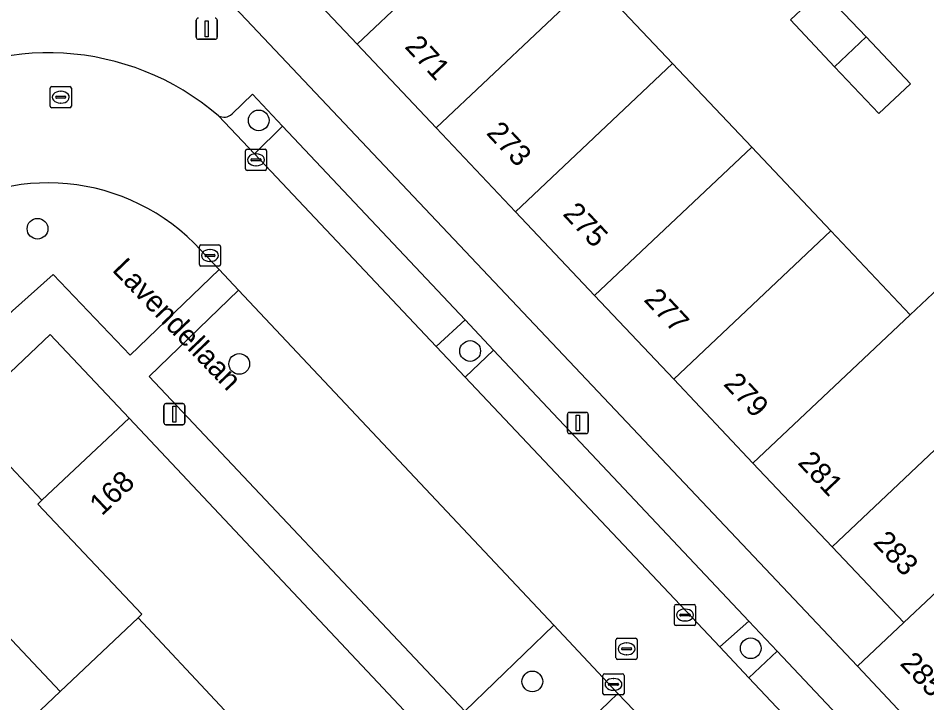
# Model space of a CAD drawing. Extents: x 162542 to 163147, y 380779 to 381521.
# Drawn here: x 162864.72 to 162907.61, y 381395.12 to 381427.46 of the extents above; entities that cross this region are included whole.
import ezdxf

# ---------------------------------------------------------------- set-up
doc = ezdxf.new("R2010")
doc.units = 0
for name, color, linetype in [('IMGEO_Boom', 7, 'Continuous'), ('IMGEO_Erf', 7, 'Continuous'), ('IMGEO_Groenvoorziening', 7, 'Continuous'), ('IMGEO_Kolk', 7, 'Continuous'), ('IMGEO_Lichtmast', 7, 'Continuous'), ('IMGEO_Openbare_ruimte_label', 7, 'Continuous'), ('IMGEO_Pand', 7, 'Continuous'), ('IMGEO_Pand_nummerreeks', 7, 'Continuous'), ('IMGEO_Parkeervlak_open', 7, 'Continuous'), ('IMGEO_Rijbaan_lokaal_open', 7, 'Continuous'), ('IMGEO_Rioolput', 7, 'Continuous'), ('IMGEO_Voetpad_open', 7, 'Continuous')]:
    doc.layers.add(name, color=color, linetype=linetype)

msp = doc.modelspace()

# ---------------------------------------------------------------- linework, layer by layer
at = {"layer": 'IMGEO_Boom'}
for centre in [(162876.075, 381422.632), (162865.636, 381417.515), (162886.055, 381411.739), (162875.156, 381411.126), (162899.298, 381397.696), (162888.991, 381396.129)]:
    msp.add_circle(centre, 0.489, dxfattribs=at)
at = {"layer": 'IMGEO_Erf'}
for points in [[(162861.159, 381432.002), (162869.05, 381439.12), (162869.767, 381438.361), (162876.917, 381445.114), (162880.655, 381441.156), (162884.393, 381437.198), (162888.132, 381433.24), (162891.87, 381429.282), (162895.608, 381425.324), (162899.346, 381421.365), (162903.084, 381417.407), (162906.823, 381413.449), (162908.963, 381415.47)], [(162851.755, 381366.101), (162878.09, 381390.885), (162870.382, 381399.141), (162866.702, 381395.654), (162862.661, 381391.825)]]:
    msp.add_lwpolyline(points, dxfattribs=at)
for points in [[(162888.193, 381418.32), (162884.455, 381422.279), (162880.718, 381426.238), (162876.98, 381430.196), (162873.243, 381434.155), (162869.505, 381438.114), (162867.324, 381436.054), (162904.333, 381396.849), (162906.52, 381398.909), (162903.143, 381402.486), (162899.406, 381406.444), (162895.668, 381410.403), (162891.93, 381414.362)], [(162902.654, 381428.781), (162904.744, 381426.573), (162906.833, 381424.364), (162905.354, 381422.952), (162903.258, 381425.167), (162901.17, 381427.375)], [(162862.119, 381408.635), (162865.839, 381404.688), (162869.957, 381408.567), (162866.239, 381412.517)]]:
    msp.add_lwpolyline(points, close=True, dxfattribs=at)
at = {"layer": 'IMGEO_Groenvoorziening'}
for points in [[(162877.202, 381422.355), (162875.775, 381423.871), (162874.815, 381422.945)], [(162874.173, 381422.854), (162875.878, 381421.045), (162877.202, 381422.355)], [(162859.95, 381417.481), (162863.931, 381413.146), (162864.454, 381413.638), (162866.374, 381415.356), (162870.009, 381411.547), (162874.208, 381415.582)], [(162874.208, 381415.582), (162873.032, 381416.833)]]:
    msp.add_lwpolyline(points, dxfattribs=at)
for points in [[(162875.124, 381414.608), (162870.912, 381410.533), (162885.812, 381394.721), (162890.007, 381398.784)], [(162887.154, 381411.783), (162885.816, 381413.205), (162884.448, 381411.957), (162885.817, 381410.504)], [(162892.608, 381395.151), (162893.031, 381395.568), (162890.007, 381398.784), (162885.812, 381394.721), (162888.818, 381391.531)], [(162900.543, 381397.562), (162899.205, 381398.982), (162897.835, 381397.758), (162899.21, 381396.299)]]:
    msp.add_lwpolyline(points, close=True, dxfattribs=at)
for centre, radius, start, end in [((162874.436, 381423.308), 0.525, 239.8967, 316.2386), ((162866.131, 381409.892), 9.788, 45.1668, 129.1617)]:
    msp.add_arc(centre, radius, start, end, dxfattribs=at)
at = {"layer": 'IMGEO_Kolk'}
for p, q in [((162875.449, 381420.344), (162875.449, 381421.196)), ((162875.524, 381421.27), (162876.376, 381421.27)), ((162875.937, 381421.05), (162875.962, 381421.05)), ((162876.45, 381421.196), (162876.45, 381420.344)), ((162875.708, 381420.764), (162875.708, 381420.776)), ((162876.146, 381420.727), (162875.748, 381420.727)), ((162875.751, 381420.813), (162876.149, 381420.813)), ((162876.192, 381420.776), (162876.192, 381420.764)), ((162876.376, 381420.27), (162875.524, 381420.27)), ((162875.96, 381420.49), (162875.935, 381420.49)), ((162873.273, 381415.822), (162873.273, 381416.674)), ((162873.348, 381416.748), (162874.2, 381416.748)), ((162874.274, 381416.674), (162874.274, 381415.822)), ((162873.532, 381416.242), (162873.532, 381416.254)), ((162873.575, 381416.291), (162873.973, 381416.291)), ((162873.761, 381416.528), (162873.786, 381416.528)), ((162874.016, 381416.254), (162874.016, 381416.242)), ((162873.97, 381416.205), (162873.572, 381416.205)), ((162873.784, 381415.968), (162873.759, 381415.968)), ((162874.2, 381415.748), (162873.348, 381415.748)), ((162895.698, 381398.84), (162895.698, 381399.692)), ((162895.773, 381399.766), (162896.625, 381399.766)), ((162896.186, 381399.546), (162896.211, 381399.546)), ((162896.699, 381399.692), (162896.699, 381398.84)), ((162895.957, 381399.26), (162895.957, 381399.272)), ((162896.395, 381399.223), (162895.997, 381399.223)), ((162896, 381399.309), (162896.398, 381399.309)), ((162896.441, 381399.272), (162896.441, 381399.26)), ((162896.625, 381398.766), (162895.773, 381398.766)), ((162896.209, 381398.986), (162896.184, 381398.986)), ((162892.321, 381395.564), (162892.321, 381396.416)), ((162892.396, 381396.49), (162893.248, 381396.49)), ((162892.809, 381396.27), (162892.834, 381396.27)), ((162893.322, 381396.416), (162893.322, 381395.564)), ((162892.58, 381395.984), (162892.58, 381395.996)), ((162893.018, 381395.947), (162892.62, 381395.947)), ((162892.623, 381396.033), (162893.021, 381396.033)), ((162892.832, 381395.71), (162892.807, 381395.71)), ((162893.064, 381395.996), (162893.064, 381395.984)), ((162893.248, 381395.49), (162892.396, 381395.49))]:
    msp.add_line(p, q, dxfattribs=at)
for points in [[(162875.449, 381420.344), (162875.449, 381421.196)], [(162875.524, 381421.27), (162876.376, 381421.27)], [(162876.45, 381421.196), (162876.45, 381420.344)], [(162876.376, 381420.27), (162875.524, 381420.27)], [(162873.273, 381415.822), (162873.273, 381416.674)], [(162873.348, 381416.748), (162874.2, 381416.748)], [(162874.274, 381416.674), (162874.274, 381415.822)], [(162874.2, 381415.748), (162873.348, 381415.748)], [(162895.698, 381398.84), (162895.698, 381399.692)], [(162895.773, 381399.766), (162896.625, 381399.766)], [(162896.699, 381399.692), (162896.699, 381398.84)], [(162896.625, 381398.766), (162895.773, 381398.766)], [(162892.321, 381395.564), (162892.321, 381396.416)], [(162892.396, 381396.49), (162893.248, 381396.49)], [(162893.322, 381396.416), (162893.322, 381395.564)], [(162893.248, 381395.49), (162892.396, 381395.49)]]:
    msp.add_lwpolyline(points, dxfattribs=at)
for centre, radius, start, end in [((162875.526, 381421.194), 0.0765, 91.552, 178.448), ((162875.526, 381421.194), 0.0765, 91.552, 178.448), ((162876.374, 381421.194), 0.0765, 1.552, 88.448), ((162876.374, 381421.194), 0.0765, 1.552, 88.448), ((162875.748, 381420.773), 0.0403, 85.8775, 175.7526), ((162875.745, 381420.763), 0.0366, 178.938, 274.7102), ((162876.149, 381420.77), 0.043, 264.8664, 352.4533), ((162876.153, 381420.775), 0.0386, 1.7309, 96.639), ((162875.526, 381420.346), 0.0765, 181.552, 268.448), ((162875.526, 381420.346), 0.0765, 181.552, 268.448), ((162876.374, 381420.346), 0.0765, 271.552, 358.448), ((162876.374, 381420.346), 0.0765, 271.552, 358.448), ((162873.35, 381416.672), 0.0765, 91.552, 178.448), ((162873.35, 381416.672), 0.0765, 91.552, 178.448), ((162874.198, 381416.672), 0.0765, 1.552, 88.448), ((162874.198, 381416.672), 0.0765, 1.552, 88.448), ((162873.572, 381416.251), 0.0403, 85.8775, 175.7526), ((162873.569, 381416.241), 0.0366, 178.938, 274.7102), ((162873.973, 381416.248), 0.043, 264.8664, 352.4533), ((162873.977, 381416.253), 0.0386, 1.7309, 96.639), ((162873.35, 381415.824), 0.0765, 181.552, 268.448), ((162873.35, 381415.824), 0.0765, 181.552, 268.448), ((162874.198, 381415.824), 0.0765, 271.552, 358.448), ((162874.198, 381415.824), 0.0765, 271.552, 358.448), ((162895.775, 381399.69), 0.0765, 91.552, 178.448), ((162895.775, 381399.69), 0.0765, 91.552, 178.448), ((162896.623, 381399.69), 0.0765, 1.552, 88.448), ((162896.623, 381399.69), 0.0765, 1.552, 88.448), ((162895.997, 381399.269), 0.0403, 85.8775, 175.7526), ((162895.994, 381399.259), 0.0366, 178.938, 274.7102), ((162896.398, 381399.266), 0.043, 264.8664, 352.4533), ((162896.402, 381399.271), 0.0386, 1.7309, 96.639), ((162895.775, 381398.842), 0.0765, 181.552, 268.448), ((162895.775, 381398.842), 0.0765, 181.552, 268.448), ((162896.623, 381398.842), 0.0765, 271.552, 358.448), ((162896.623, 381398.842), 0.0765, 271.552, 358.448), ((162892.398, 381396.414), 0.0765, 91.552, 178.448), ((162892.398, 381396.414), 0.0765, 91.552, 178.448), ((162893.246, 381396.414), 0.0765, 1.552, 88.448), ((162893.246, 381396.414), 0.0765, 1.552, 88.448), ((162892.62, 381395.993), 0.0403, 85.8775, 175.7526), ((162892.617, 381395.983), 0.0366, 178.938, 274.7102), ((162893.021, 381395.99), 0.043, 264.8664, 352.4533), ((162893.025, 381395.995), 0.0386, 1.7309, 96.639), ((162892.398, 381395.566), 0.0765, 181.552, 268.448), ((162892.398, 381395.566), 0.0765, 181.552, 268.448), ((162893.246, 381395.566), 0.0765, 271.552, 358.448), ((162893.246, 381395.566), 0.0765, 271.552, 358.448)]:
    msp.add_arc(centre, radius, start, end, dxfattribs=at)
for centre, major_axis, ratio, start_param, end_param in [((162875.936, 381420.77), (-0.387, 0.002), 0.722429, 4.712389, 7.853982), ((162875.961, 381420.77), (-0.39, 0.002), 0.717154, 1.570796, 4.712389), ((162873.76, 381416.248), (-0.387, 0.002), 0.722429, 4.712389, 7.853982), ((162873.785, 381416.248), (-0.39, 0.002), 0.717154, 1.570796, 4.712389), ((162896.185, 381399.266), (-0.387, 0.002), 0.722429, 4.712389, 7.853982), ((162896.21, 381399.266), (-0.39, 0.002), 0.717154, 1.570796, 4.712389), ((162892.808, 381395.99), (-0.387, 0.002), 0.722429, 4.712389, 7.853982), ((162892.833, 381395.99), (-0.39, 0.002), 0.717154, 1.570796, 4.712389)]:
    msp.add_ellipse(centre, major_axis=major_axis, ratio=ratio, start_param=start_param, end_param=end_param, dxfattribs=at)
at = {"layer": 'IMGEO_Lichtmast'}
for p, q in [((162873.127, 381426.561), (162873.127, 381427.361)), ((162873.127, 381427.361), (162873.127, 381426.561)), ((162874.117, 381427.361), (162874.117, 381426.561)), ((162874.117, 381426.561), (162874.117, 381427.361)), ((162874.017, 381426.461), (162873.227, 381426.461)), ((162873.227, 381426.461), (162874.017, 381426.461)), ((162871.598, 381408.354), (162871.598, 381409.154)), ((162871.598, 381409.154), (162871.598, 381408.354)), ((162871.698, 381409.254), (162872.488, 381409.254)), ((162872.488, 381409.254), (162871.698, 381409.254)), ((162872.588, 381409.154), (162872.588, 381408.354)), ((162872.588, 381408.354), (162872.588, 381409.154)), ((162890.644, 381407.936), (162890.644, 381408.736)), ((162890.644, 381408.736), (162890.644, 381407.936)), ((162890.744, 381408.836), (162891.534, 381408.836)), ((162891.534, 381408.836), (162890.744, 381408.836)), ((162891.634, 381408.736), (162891.634, 381407.936)), ((162891.634, 381407.936), (162891.634, 381408.736)), ((162872.488, 381408.254), (162871.698, 381408.254)), ((162871.698, 381408.254), (162872.488, 381408.254)), ((162891.534, 381407.836), (162890.744, 381407.836)), ((162890.744, 381407.836), (162891.534, 381407.836))]:
    msp.add_line(p, q, dxfattribs=at)
for points in [[(162873.547, 381427.336), (162873.697, 381427.336), (162873.697, 381426.586), (162873.547, 381426.586), (162873.547, 381427.336)], [(162872.018, 381409.129), (162872.168, 381409.129), (162872.168, 381408.379), (162872.018, 381408.379), (162872.018, 381409.129)], [(162891.064, 381408.711), (162891.214, 381408.711), (162891.214, 381407.961), (162891.064, 381407.961), (162891.064, 381408.711)]]:
    msp.add_lwpolyline(points, dxfattribs=at)
for centre, start, end in [((162873.227, 381427.361), 90, 180), ((162873.227, 381427.361), 90, 180), ((162874.017, 381427.361), 0, 90), ((162874.017, 381427.361), 360, 90), ((162873.227, 381426.561), 180, 270), ((162873.227, 381426.561), 180, 270), ((162874.017, 381426.561), 270, 0), ((162874.017, 381426.561), 270, 0), ((162871.698, 381409.154), 90, 180), ((162871.698, 381409.154), 90, 180), ((162872.488, 381409.154), 0, 90), ((162872.488, 381409.154), 360, 90), ((162890.744, 381408.736), 90, 180), ((162890.744, 381408.736), 90, 180), ((162891.534, 381408.736), 0, 90), ((162891.534, 381408.736), 360, 90), ((162871.698, 381408.354), 180, 270), ((162871.698, 381408.354), 180, 270), ((162872.488, 381408.354), 270, 0), ((162872.488, 381408.354), 270, 0), ((162890.744, 381407.936), 180, 270), ((162890.744, 381407.936), 180, 270), ((162891.534, 381407.936), 270, 0), ((162891.534, 381407.936), 270, 0)]:
    msp.add_arc(centre, 0.1, start, end, dxfattribs=at)
at = {"layer": 'IMGEO_Pand'}
for points in [[(162888.132, 381433.24), (162884.393, 381437.198), (162876.98, 381430.196), (162880.718, 381426.238)], [(162891.87, 381429.282), (162888.132, 381433.24), (162880.718, 381426.238), (162884.455, 381422.279)], [(162895.608, 381425.324), (162891.87, 381429.282), (162884.455, 381422.279), (162888.193, 381418.32)], [(162902.654, 381428.781), (162901.17, 381427.375), (162903.258, 381425.167), (162904.744, 381426.573)], [(162904.744, 381426.573), (162903.258, 381425.167), (162905.354, 381422.952), (162906.833, 381424.364)], [(162899.346, 381421.365), (162895.608, 381425.324), (162888.193, 381418.32), (162891.93, 381414.362)], [(162903.084, 381417.407), (162899.346, 381421.365), (162891.93, 381414.362), (162895.668, 381410.403)], [(162906.823, 381413.449), (162903.084, 381417.407), (162895.668, 381410.403), (162899.406, 381406.444)], [(162910.561, 381409.491), (162910.494, 381409.562), (162911.883, 381410.971), (162911.792, 381412.475), (162908.963, 381415.47), (162906.823, 381413.449), (162899.406, 381406.444), (162903.143, 381402.486)], [(162914.299, 381405.533), (162910.561, 381409.491), (162903.143, 381402.486), (162906.52, 381398.909), (162911.747, 381403.833), (162912.099, 381403.46)], [(162865.644, 381404.504), (162865.839, 381404.688), (162862.119, 381408.635), (162858.067, 381404.817), (162866.702, 381395.654), (162870.382, 381399.141), (162870.563, 381399.312)], [(162869.957, 381408.567), (162865.839, 381404.688), (162865.644, 381404.504), (162870.563, 381399.312), (162870.382, 381399.141), (162878.09, 381390.885), (162878.428, 381390.523), (162882.947, 381394.764)], [(162858.067, 381404.817), (162854.016, 381400.999), (162862.661, 381391.825), (162866.702, 381395.654)], [(162915.569, 381399.779), (162912.099, 381403.46), (162911.747, 381403.833), (162906.52, 381398.909), (162904.333, 381396.849), (162908.153, 381392.793)]]:
    msp.add_lwpolyline(points, close=True, dxfattribs=at)
at = {"layer": 'IMGEO_Parkeervlak_open'}
for points in [[(162877.202, 381422.355), (162875.878, 381421.045), (162884.448, 381411.957), (162885.816, 381413.205)], [(162887.154, 381411.783), (162885.817, 381410.504), (162897.835, 381397.758), (162899.205, 381398.982)], [(162900.543, 381397.562), (162899.21, 381396.299), (162915.46, 381379.065), (162916.781, 381380.313)]]:
    msp.add_lwpolyline(points, close=True, dxfattribs=at)
at = {"layer": 'IMGEO_Rijbaan_lokaal_open'}
for points in [[(162899.21, 381396.299), (162897.835, 381397.758), (162885.817, 381410.504), (162884.448, 381411.957), (162875.878, 381421.045), (162874.173, 381422.854)], [(162873.032, 381416.833), (162874.208, 381415.582), (162875.124, 381414.608), (162890.007, 381398.784), (162893.031, 381395.568), (162897.205, 381391.195), (162900.36, 381387.84), (162912.37, 381375.072), (162916.012, 381378.48), (162915.46, 381379.065), (162899.21, 381396.299)]]:
    msp.add_lwpolyline(points, dxfattribs=at)
for centre, radius, start, end in [((162866.14, 381413.478), 12.347, 49.4131, 123.8549), ((162866.131, 381409.892), 9.788, 45.1668, 129.1617)]:
    msp.add_arc(centre, radius, start, end, dxfattribs=at)
at = {"layer": 'IMGEO_Rioolput'}
for p, q in [((162866.232, 381423.301), (162866.232, 381424.153)), ((162866.307, 381424.227), (162867.159, 381424.227)), ((162866.72, 381424.007), (162866.745, 381424.007)), ((162867.233, 381424.153), (162867.233, 381423.301)), ((162866.491, 381423.721), (162866.491, 381423.733)), ((162866.929, 381423.684), (162866.531, 381423.684)), ((162866.534, 381423.77), (162866.932, 381423.77)), ((162866.975, 381423.733), (162866.975, 381423.721)), ((162867.159, 381423.227), (162866.307, 381423.227)), ((162866.743, 381423.447), (162866.718, 381423.447)), ((162892.94, 381397.243), (162892.94, 381398.095)), ((162893.015, 381398.169), (162893.867, 381398.169)), ((162893.428, 381397.949), (162893.453, 381397.949)), ((162893.941, 381398.095), (162893.941, 381397.243)), ((162893.199, 381397.663), (162893.199, 381397.675)), ((162893.637, 381397.626), (162893.239, 381397.626)), ((162893.242, 381397.712), (162893.64, 381397.712)), ((162893.451, 381397.389), (162893.426, 381397.389)), ((162893.683, 381397.675), (162893.683, 381397.663)), ((162893.867, 381397.169), (162893.015, 381397.169))]:
    msp.add_line(p, q, dxfattribs=at)
for points in [[(162866.232, 381423.301), (162866.232, 381424.153)], [(162866.307, 381424.227), (162867.159, 381424.227)], [(162867.233, 381424.153), (162867.233, 381423.301)], [(162867.159, 381423.227), (162866.307, 381423.227)], [(162892.94, 381397.243), (162892.94, 381398.095)], [(162893.015, 381398.169), (162893.867, 381398.169)], [(162893.941, 381398.095), (162893.941, 381397.243)], [(162893.867, 381397.169), (162893.015, 381397.169)]]:
    msp.add_lwpolyline(points, dxfattribs=at)
for centre, radius, start, end in [((162866.309, 381424.151), 0.0765, 91.552, 178.448), ((162866.309, 381424.151), 0.0765, 91.552, 178.448), ((162867.157, 381424.151), 0.0765, 1.552, 88.448), ((162867.157, 381424.151), 0.0765, 1.552, 88.448), ((162866.531, 381423.73), 0.0403, 85.8775, 175.7526), ((162866.528, 381423.72), 0.0366, 178.938, 274.7102), ((162866.932, 381423.727), 0.043, 264.8664, 352.4533), ((162866.936, 381423.732), 0.0386, 1.7309, 96.639), ((162866.309, 381423.303), 0.0765, 181.552, 268.448), ((162866.309, 381423.303), 0.0765, 181.552, 268.448), ((162867.157, 381423.303), 0.0765, 271.552, 358.448), ((162867.157, 381423.303), 0.0765, 271.552, 358.448), ((162893.017, 381398.093), 0.0765, 91.552, 178.448), ((162893.017, 381398.093), 0.0765, 91.552, 178.448), ((162893.865, 381398.093), 0.0765, 1.552, 88.448), ((162893.865, 381398.093), 0.0765, 1.552, 88.448), ((162893.239, 381397.672), 0.0403, 85.8775, 175.7526), ((162893.236, 381397.662), 0.0366, 178.938, 274.7102), ((162893.64, 381397.669), 0.043, 264.8664, 352.4533), ((162893.644, 381397.674), 0.0386, 1.7309, 96.639), ((162893.017, 381397.245), 0.0765, 181.552, 268.448), ((162893.017, 381397.245), 0.0765, 181.552, 268.448), ((162893.865, 381397.245), 0.0765, 271.552, 358.448), ((162893.865, 381397.245), 0.0765, 271.552, 358.448)]:
    msp.add_arc(centre, radius, start, end, dxfattribs=at)
for centre, major_axis, ratio, start_param, end_param in [((162866.719, 381423.727), (-0.387, 0.002), 0.722429, 4.712389, 7.853982), ((162866.744, 381423.727), (-0.39, 0.002), 0.717154, 1.570796, 4.712389), ((162893.427, 381397.669), (-0.387, 0.002), 0.722429, 4.712389, 7.853982), ((162893.452, 381397.669), (-0.39, 0.002), 0.717154, 1.570796, 4.712389)]:
    msp.add_ellipse(centre, major_axis=major_axis, ratio=ratio, start_param=start_param, end_param=end_param, dxfattribs=at)
at = {"layer": 'IMGEO_Voetpad_open'}
for points in [[(162911.974, 381388.738), (162908.153, 381392.793), (162904.333, 381396.849), (162867.324, 381436.054), (162869.505, 381438.114), (162869.767, 381438.361), (162869.05, 381439.12), (162861.159, 381432.002), (162859.586, 381433.676), (162859.038, 381433.161), (162858.949, 381433.255), (162856.034, 381430.516), (162856.123, 381430.422), (162855.576, 381429.908), (162857.637, 381427.714), (162849.743, 381420.296), (162845.564, 381416.369), (162841.367, 381412.426), (162837.186, 381408.498), (162833.031, 381404.902)], [(162874.815, 381422.945), (162875.775, 381423.871), (162877.202, 381422.355), (162885.816, 381413.205), (162887.154, 381411.783), (162899.205, 381398.982), (162900.543, 381397.562), (162916.781, 381380.313), (162918.098, 381378.914), (162917.098, 381378.024)], [(162862.119, 381408.635), (162866.239, 381412.517), (162869.957, 381408.567), (162882.947, 381394.764), (162883.582, 381394.089), (162887.127, 381390.321), (162891.278, 381385.908), (162893.039, 381387.172), (162896.723, 381390.77), (162897.205, 381391.195), (162893.031, 381395.568), (162892.608, 381395.151), (162888.818, 381391.531), (162885.812, 381394.721), (162870.912, 381410.533), (162875.124, 381414.608), (162874.208, 381415.582), (162870.009, 381411.547), (162866.374, 381415.356), (162864.454, 381413.638)]]:
    msp.add_lwpolyline(points, dxfattribs=at)
for centre, radius, start, end in [((162866.14, 381413.478), 12.347, 49.4131, 123.8549), ((162874.436, 381423.308), 0.525, 239.8967, 316.2386)]:
    msp.add_arc(centre, radius, start, end, dxfattribs=at)

# ---------------------------------------------------------------- texts
at = {"layer": 'IMGEO_Openbare_ruimte_label'}
msp.add_text('Lavendellaan', height=1, rotation=313.7846, dxfattribs=at).set_placement((162869.117, 381415.541))
at = {"layer": 'IMGEO_Pand_nummerreeks'}
for s, rotation, p in [('271', 313.1492, (162882.931, 381426.085)), ('273', 313.155, (162886.781, 381422.007)), ('275', 313.155, (162890.389, 381418.186)), ('277', 313.155, (162894.214, 381414.134)), ('279', 313.155, (162897.975, 381410.151)), ('281', 313.155, (162901.483, 381406.436)), ('168', 43.287, (162868.669, 381403.92)), ('283', 313.155, (162905.038, 381402.671)), ('285', 313.0862, (162906.306, 381396.948))]:
    msp.add_text(s, height=1, rotation=rotation, dxfattribs=at).set_placement(p)

doc.saveas('drawing.dxf')
